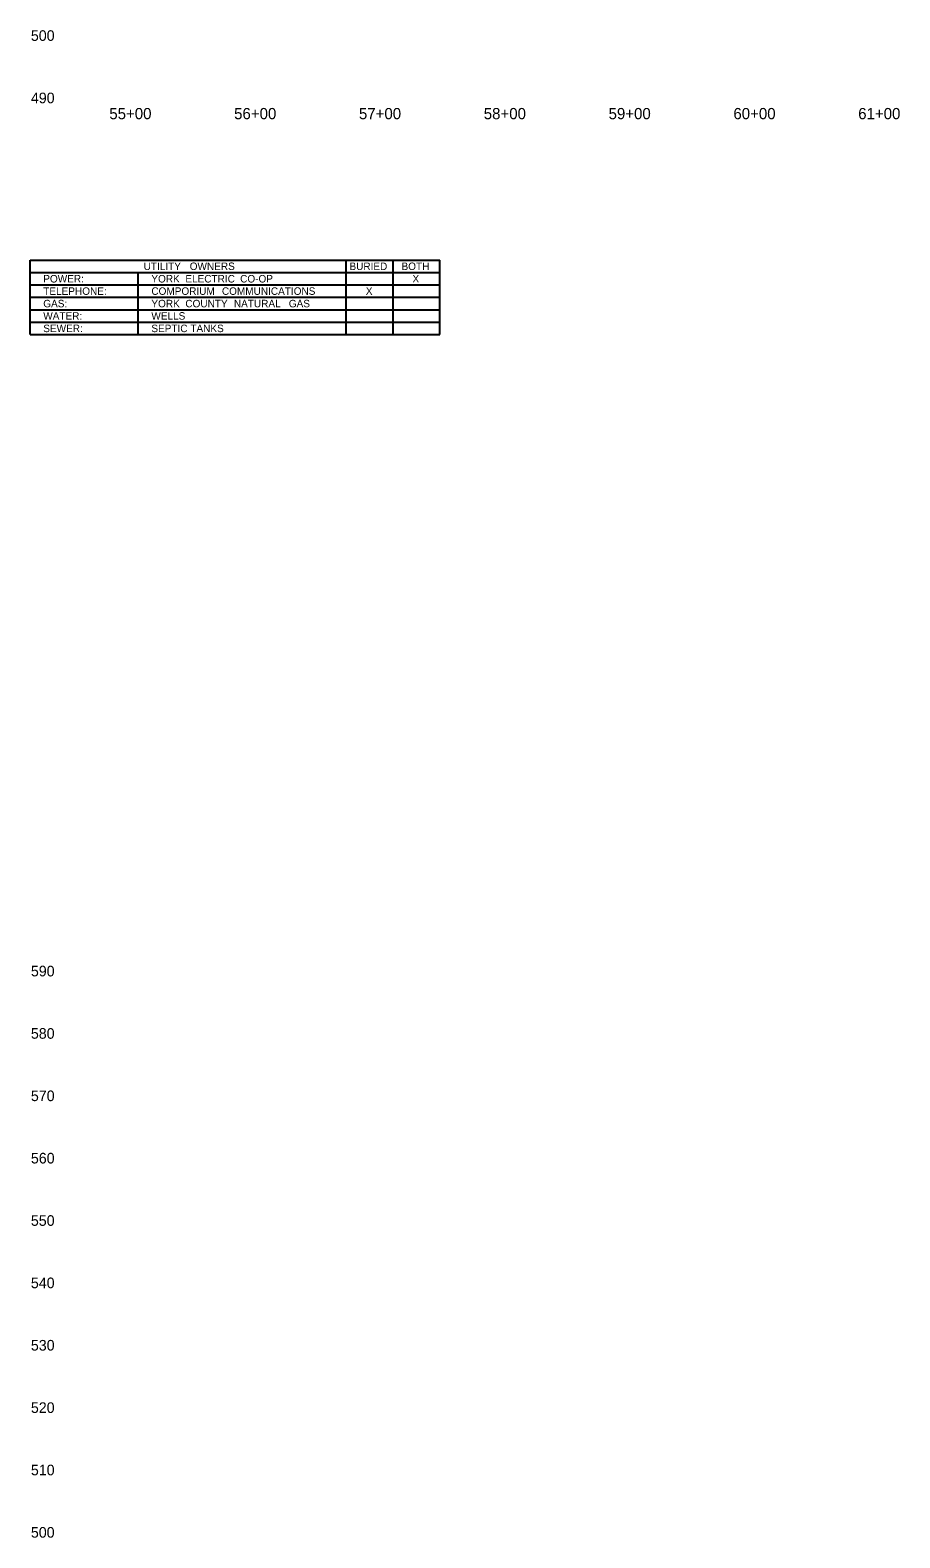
# Model space of a CAD drawing. Extents: x 1964849 to 1967422, y 1116563 to 1122210.
# Drawn here: x 1965765 to 1966462, y 1116575 to 1117784 of the extents above; entities that cross this region are included whole.
import ezdxf

# ---------------------------------------------------------------- set-up
doc = ezdxf.new("R2010")
doc.units = 0
for name, color, linetype in [('RD_DDB_Profile_Elev', 7, 'Continuous'), ('RD_DDB_StaTX', 7, 'Continuous'), ('RD_SHT_TX', 7, 'Continuous'), ('RD_TX_Misc1', 7, 'Continuous')]:
    doc.layers.add(name, color=color, linetype=linetype)

msp = doc.modelspace()

# ---------------------------------------------------------------- linework, layer by layer
at = {"layer": 'RD_SHT_TX'}
msp.add_line((1965765.3, 1117599.8), (1965765.3, 1117599.8), dxfattribs=at)
at = {"layer": 'RD_TX_Misc1'}
for p, q in [((1965765.3, 1117599.8), (1966093.5, 1117599.8)), ((1965765.3, 1117540.2), (1965765.3, 1117599.8)), ((1966018.6, 1117540.2), (1966018.6, 1117599.8)), ((1966056.1, 1117540.2), (1966056.1, 1117599.8)), ((1966093.5, 1117540.2), (1966093.5, 1117599.8)), ((1965765.3, 1117589.9), (1966093.5, 1117589.9)), ((1965851.9, 1117540.2), (1965851.9, 1117589.9)), ((1965765.3, 1117580), (1966093.5, 1117580)), ((1965765.3, 1117570), (1966093.5, 1117570)), ((1965765.3, 1117560.1), (1966093.5, 1117560.1)), ((1965765.3, 1117550.1), (1966093.5, 1117550.1)), ((1965765.3, 1117540.2), (1966093.5, 1117540.2))]:
    msp.add_line(p, q, dxfattribs=at)

# ---------------------------------------------------------------- texts
at = {"layer": 'RD_DDB_Profile_Elev'}
for s, p in [('500', (1965765.9, 1117775.6)), ('490', (1965765.9, 1117725.6)), ('590', (1965765.9, 1117025.6)), ('580', (1965765.9, 1116975.6)), ('570', (1965765.9, 1116925.6)), ('560', (1965765.9, 1116875.6)), ('550', (1965765.9, 1116825.6)), ('540', (1965765.9, 1116775.6)), ('530', (1965765.9, 1116725.6)), ('520', (1965765.9, 1116675.6)), ('510', (1965765.9, 1116625.6)), ('500', (1965765.9, 1116575.6))]:
    msp.add_text(s, height=8.5, dxfattribs=at).set_placement(p)
at = {"layer": 'RD_DDB_StaTX'}
for s, p in [('55+00', (1965828.7, 1117712.8)), ('56+00', (1965928.7, 1117712.8)), ('57+00', (1966028.7, 1117712.8)), ('58+00', (1966128.7, 1117712.8)), ('59+00', (1966228.7, 1117712.8)), ('60+00', (1966328.7, 1117712.8)), ('61+00', (1966428.7, 1117712.8))]:
    msp.add_text(s, height=9, dxfattribs=at).set_placement(p)
at = {"layer": 'RD_TX_Misc1'}
for s, p in [(' UTILITY', (1965854, 1117591.9)), (' OWNERS', (1965890.9, 1117591.9)), ('BURIED', (1966021.1, 1117591.9)), ('BOTH', (1966062.8, 1117591.9)), ('POWER:', (1965775.8, 1117581.9)), ('YORK', (1965862.4, 1117581.9)), (' ELECTRIC', (1965887.4, 1117581.9)), (' CO-OP', (1965931.3, 1117581.9)), ('X', (1966071.6, 1117581.9)), ('TELEPHONE:', (1965775.8, 1117572)), ('COMPORIUM', (1965862.4, 1117572)), (' COMMUNICATIONS', (1965916.7, 1117572)), ('X', (1966034.2, 1117572)), ('GAS:', (1965775.8, 1117562)), ('YORK', (1965862.4, 1117562)), (' COUNTY', (1965887.4, 1117562)), (' NATURAL', (1965926.3, 1117562)), (' GAS', (1965970.3, 1117562)), ('WATER:', (1965775.8, 1117552.1)), ('SEWER:', (1965775.8, 1117542.1)), ('WELLS', (1965862.4, 1117552.1)), ('SEPTIC', (1965862.4, 1117542.1)), (' TANKS', (1965891.4, 1117542.1))]:
    msp.add_text(s, height=6, dxfattribs=at).set_placement(p)

doc.saveas('drawing.dxf')
